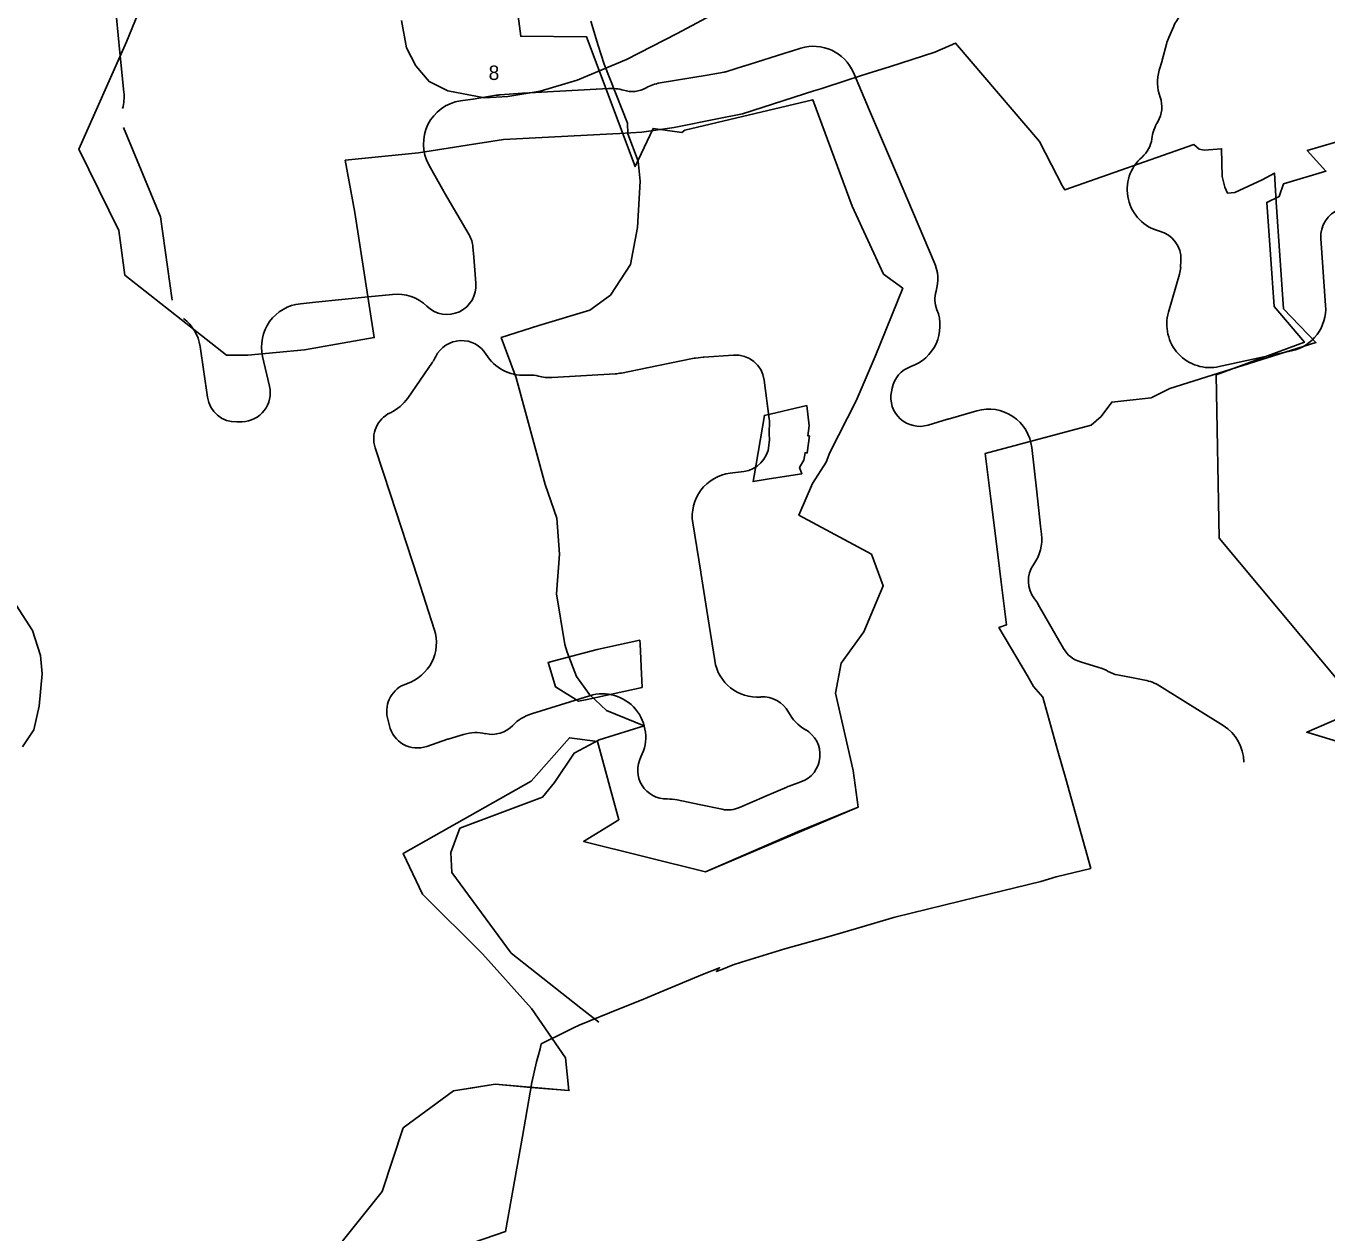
# Model space of a CAD drawing. Extents: x -445049 to -436194, y -1142460 to -1129816.
# Drawn here: x -443023 to -442122, y -1133134 to -1132297 of the extents above; entities that cross this region are included whole.
import ezdxf

# ---------------------------------------------------------------- set-up
doc = ezdxf.new("R2010")
doc.units = 0
for name, color, linetype in [('Vrstva 10', 7, 'Continuous'), ('Vrstva 23', 7, 'Continuous'), ('Vrstva 26', 7, 'Continuous'), ('Vrstva 51', 7, 'Continuous'), ('Vrstva 7', 7, 'Continuous'), ('Vrstva 8', 7, 'Continuous'), ('Vrstva 9', 7, 'Continuous')]:
    doc.layers.add(name, color=color, linetype=linetype)

msp = doc.modelspace()

# ---------------------------------------------------------------- linework, layer by layer
at = {"layer": 'Vrstva 10'}
msp.add_lwpolyline([(-442109.03, -1132794.68), (-442135.55, -1132786.74), (-442097.52, -1132770.3), (-442196.18, -1132652.14), (-442198.38, -1132539.08), (-442137.12, -1132516.56), (-442158.19, -1132491.81), (-442163.27, -1132419.71), (-442154.54, -1132415.62), (-442151.59, -1132406.77), (-442122.25, -1132397.95), (-442135.23, -1132383.63), (-442097.99, -1132372.93)], dxfattribs=at)
at = {"layer": 'Vrstva 23'}
for p, q in [((-442957.74, -1132315.82), (-442960.18, -1132291.9)), ((-442227.66, -1132297.45), (-442231.2, -1132305.52)), ((-442232.75, -1132310.02), (-442235.63, -1132321.09)), ((-442954.94, -1132343.31), (-442957.74, -1132315.82)), ((-442493.43, -1132315.14), (-442525.56, -1132325.32)), ((-442486.1, -1132312.86), (-442493.26, -1132315.09)), ((-442235.8, -1132321.69), (-442237.68, -1132328.11)), ((-442539.18, -1132329.4), (-442550.89, -1132331.43)), ((-442525.63, -1132325.34), (-442536.62, -1132328.79)), ((-442438.41, -1132355.92), (-442449.62, -1132329.71)), ((-442551.01, -1132331.46), (-442583.52, -1132336.89)), ((-442713.29, -1132348.06), (-442721.83, -1132349.33)), ((-442696.97, -1132345.45), (-442713.06, -1132348.03)), ((-442678.78, -1132344.02), (-442694.4, -1132345.15)), ((-442619.3, -1132340.69), (-442678.28, -1132343.99)), ((-442419.09, -1132401.26), (-442438.4, -1132355.96)), ((-442743.65, -1132393.58), (-442733.12, -1132412.52)), ((-442393.54, -1132460.98), (-442419.08, -1132401.29)), ((-442732.79, -1132413.1), (-442715.81, -1132442.13)), ((-442122.5, -1132491.05), (-442125.76, -1132444.58)), ((-442713.13, -1132450.74), (-442712.63, -1132457.45)), ((-442712.62, -1132457.65), (-442711.15, -1132475.65)), ((-442222.69, -1132459.74), (-442222.89, -1132464.67)), ((-442223.67, -1132469.45), (-442231.32, -1132495.7)), ((-442768.9, -1132483.34), (-442785.65, -1132485.04)), ((-442822.34, -1132488.76), (-442832.71, -1132489.83)), ((-442785.65, -1132485.04), (-442822.28, -1132488.75)), ((-442897.11, -1132554.65), (-442902.23, -1132519.43)), ((-442858.87, -1132526.42), (-442854.12, -1132547)), ((-442592.49, -1132534.2), (-442560.97, -1132527.8)), ((-442559.04, -1132527.5), (-442553.72, -1132526.95)), ((-442553.15, -1132526.9), (-442532.68, -1132525.39)), ((-442196.12, -1132533.4), (-442146.02, -1132522.46)), ((-442758.36, -1132555.17), (-442741.27, -1132530.36)), ((-442741.27, -1132530.35), (-442741.17, -1132530.21)), ((-442610.33, -1132537.86), (-442592.53, -1132534.2)), ((-442676.81, -1132539.4), (-442674.08, -1132539.27)), ((-442658.19, -1132540.96), (-442614.62, -1132538.42)), ((-442511.38, -1132542.74), (-442507.85, -1132569.69)), ((-442423.3, -1132550.9), (-442422.8, -1132548.36)), ((-442364.18, -1132564.03), (-442383.92, -1132569.71)), ((-442872.96, -1132571.65), (-442876.71, -1132571.76)), ((-442384.3, -1132569.83), (-442397.89, -1132573.94)), ((-442770.36, -1132621.97), (-442780.93, -1132589.7)), ((-442507.87, -1132585.65), (-442508.11, -1132588.09)), ((-442322.63, -1132620.13), (-442326.06, -1132589.51)), ((-442525.49, -1132606.01), (-442535.04, -1132607.23)), ((-442751.63, -1132679.36), (-442770.35, -1132622)), ((-442319.97, -1132643.84), (-442322.63, -1132620.14)), ((-442560.87, -1132641.74), (-442555.38, -1132675.91)), ((-442319.32, -1132649.42), (-442319.96, -1132643.94)), ((-442739.92, -1132715.25), (-442751.62, -1132679.37)), ((-442555.37, -1132675.96), (-442550.51, -1132706.63)), ((-442304.03, -1132728.71), (-442321.53, -1132698.1)), ((-442550.51, -1132706.63), (-442545.69, -1132737.06)), ((-442279.61, -1132741.74), (-442292.35, -1132737.96)), ((-442255.77, -1132749.05), (-442266.65, -1132746.98)), ((-442247.76, -1132750.57), (-442255.77, -1132749.05)), ((-442632.38, -1132761.4), (-442672.71, -1132773.93)), ((-442193.37, -1132782.02), (-442237.52, -1132754.57)), ((-442771.06, -1132782.17), (-442772.36, -1132776.66)), ((-442719.65, -1132788.24), (-442729.71, -1132791.27)), ((-442730.73, -1132791.6), (-442745.14, -1132796.51)), ((-442495.73, -1132824.7), (-442511.06, -1132831.2)), ((-442485.94, -1132821.12), (-442494.19, -1132824.1)), ((-442556.5, -1132836.74), (-442571.71, -1132833.56)), ((-442511.41, -1132831.35), (-442528.41, -1132838.82)), ((-442540.54, -1132840.08), (-442556.5, -1132836.74))]:
    msp.add_line(p, q, dxfattribs=at)
msp.add_lwpolyline([(-442921.64, -1132487.44), (-442929.57, -1132429.68), (-442955.18, -1132367.68)], dxfattribs=at)
for centre, radius, start, end in [((-442200.18, -1132309.49), 30, 136.62933, 156.33647), ((-442477.2, -1132341.51), 30, 23.15168, 107.25965), ((-442203.72, -1132317.56), 30, 156.33647, 165.43444), ((-442937.84, -1132313.79), 20, 185.82227, 185.82544), ((-442484.36, -1132343.73), 30, 107.25965, 107.58988), ((-442254.99, -1132316.06), 20, 343.64627, 345.43444), ((-442542.6, -1132309.7), 20, 279.83922, 287.37641), ((-442531.6, -1132306.26), 20, 287.37641, 287.58988), ((-442208.89, -1132336.55), 30, 163.64627, 199.84662), ((-442578.57, -1132366.48), 30, 99.49232, 119.21234), ((-442554.31, -1132311.73), 20, 279.49232, 279.83922), ((-442984.78, -1132346.35), 30, 344.10309, 5.82544), ((-442716.22, -1132328.28), 20, 278.44397, 279.08948), ((-442692.23, -1132375.07), 30, 94.15381, 99.08948), ((-442676.61, -1132373.94), 30, 93.19748, 94.15381), ((-442617.62, -1132370.64), 30, 72.95959, 93.19748), ((-442602.97, -1132322.84), 20, 252.95959, 299.21234), ((-442255.92, -1132353.53), 20, 328.95738, 19.84662), ((-442717.43, -1132379), 30, 98.44397, 209.06864), ((-442466, -1132367.72), 30, 23.07993, 23.15168), ((-442212.78, -1132379.49), 30.35, 148.95738, 172.76176), ((-442262.73, -1132373.15), 20, 310.92226, 352.76176), ((-442230.13, -1132410.76), 29.77, 130.92226, 255.41229), ((-442400.69, -1132393.42), 20, 203.07993, 203.16557), ((-442706.9, -1132397.95), 30, 209.06864, 210.32596), ((-442105.81, -1132443.17), 20, 110.6205, 184.01796), ((-442191.84, -1132439.88), 50, 177.60823, 177.64508), ((-442733.08, -1132452.22), 20, 4.259, 30.32596), ((-442242.67, -1132458.92), 20, 357.64508, 75.41229), ((-442682.71, -1132455.22), 30, 184.25897, 184.65397), ((-442421.12, -1132472.78), 30, 343.82915, 23.16557), ((-442242.87, -1132463.85), 20, 343.74529, 357.64508), ((-442765.87, -1132513.19), 30, 45.9152, 95.7926), ((-442731.08, -1132477.27), 20, 225.9152, 4.65396), ((-442373.1, -1132486.71), 20, 163.82915, 201.5094), ((-442829.64, -1132519.67), 30, 95.88775, 192.9966), ((-442819.26, -1132518.6), 30, 95.78982, 95.88775), ((-442787.67, -1132465.14), 20, 275.78982, 275.7926), ((-442152.42, -1132493.15), 30, 282.32123, 4.01796), ((-442931.92, -1132523.75), 30, 8.27726, 52.36246), ((-442419.62, -1132505.04), 30, 289.19359, 21.5094), ((-442202.52, -1132504.09), 30, 163.74529, 282.32123), ((-442721.06, -1132535.36), 20, 31.22603, 153.67299), ((-442765.87, -1132513.19), 30, 325.43977, 333.67299), ((-442678.3, -1132509.44), 30, 211.22603, 272.84214), ((-442556.99, -1132547.4), 20, 95.88585, 101.47902), ((-442551.67, -1132546.85), 20, 94.23101, 95.88585), ((-442531.21, -1132545.33), 20, 7.46163, 94.23101), ((-442724.8, -1132541.7), 20, 145.43977, 145.44951), ((-442616.36, -1132508.47), 30, 273.3252, 281.61099), ((-442588.5, -1132553.8), 20, 101.47902, 101.61099), ((-442403.18, -1132552.26), 20, 109.19359, 168.76185), ((-442673.09, -1132559.24), 20, 74.74496, 92.84214), ((-442659.93, -1132511.01), 30, 254.74496, 273.3252), ((-442877.32, -1132551.77), 20, 188.27726, 271.74737), ((-442873.57, -1132551.66), 20, 271.74737, 13.18493), ((-442824.89, -1132540.25), 30, 192.9966, 193.18493), ((-442783.07, -1132538.16), 30, 295.00864, 325.44951), ((-442403.68, -1132554.8), 20, 168.76185, 286.83942), ((-442355.87, -1132592.85), 30, 6.39032, 106.07109), ((-442761.93, -1132583.47), 20, 115.00864, 198.13953), ((-442527.68, -1132572.29), 20, 353.04978, 7.46163), ((-442375.61, -1132598.54), 30, 106.07109, 106.83942), ((-442478.05, -1132578.34), 30, 173.04978, 186.09223), ((-442527.76, -1132583.64), 20, 354.25098, 6.09223), ((-442528.02, -1132586.17), 20, 277.27102, 354.34773), ((-442478.26, -1132591.09), 30, 174.25098, 174.34773), ((-442531.25, -1132636.98), 30, 97.27102, 189.13006), ((-442798.87, -1132631.31), 30, 18.08071, 18.13953), ((-442302.75, -1132617.91), 20, 186.39032, 186.3974), ((-442300.09, -1132641.61), 20, 186.3974, 186.6774), ((-442349.11, -1132652.91), 30, 324.52822, 6.6774), ((-442308.39, -1132681.93), 20, 144.52822, 218.41396), ((-442780.14, -1132688.67), 30, 18.05894, 18.08071), ((-442575.12, -1132679.08), 20, 8.99993, 9.13006), ((-442347.57, -1132712.99), 30, 29.76045, 38.41396), ((-442570.26, -1132709.76), 20, 8.99472, 8.99993), ((-442768.45, -1132724.55), 30, 288.12384, 18.05894), ((-442286.66, -1132718.79), 20, 209.75853, 253.49032), ((-442516.06, -1132732.37), 30, 188.99472, 274.36892), ((-442288.14, -1132770.5), 30, 59.69874, 73.49032), ((-442262.91, -1132727.33), 20, 239.69874, 259.22819), ((-442752.89, -1132772.07), 20, 108.12384, 193.25843), ((-442252.03, -1132729.4), 20, 259.22819, 259.2388), ((-442253.36, -1132780.04), 30, 58.12147, 79.2388), ((-442623.48, -1132790.05), 30, 332.75604, 107.25158), ((-442512.25, -1132782.22), 20, 27.9218, 94.36892), ((-442663.81, -1132802.58), 30, 107.25158, 136.50496), ((-442468.07, -1132758.81), 30, 207.9218, 240.46264), ((-442751.59, -1132777.58), 20, 193.25843, 288.82418), ((-442710.98, -1132816.96), 30, 77.4082, 106.78491), ((-442700.08, -1132768.16), 20, 257.4082, 316.50496), ((-442492.72, -1132802.31), 20, 289.82444, 60.46264), ((-442209.21, -1132807.5), 30, 0.15915, 58.12147), ((-442721.05, -1132820), 30, 106.78491, 108.82418), ((-442579.03, -1132812.94), 20, 152.75604, 271.35626), ((-442484.02, -1132852.32), 30, 109.82444, 112.97972), ((-442577.85, -1132862.93), 30, 78.18999, 91.35626), ((-442499.35, -1132858.82), 30, 112.97972, 113.70018), ((-442552.41, -1132817.17), 20, 258.18999, 258.19838), ((-442536.45, -1132820.5), 20, 258.19838, 293.70018)]:
    msp.add_arc(centre, radius, start, end, dxfattribs=at)
at = {"layer": 'Vrstva 26'}
for points in [[(-442631.56, -1132294), (-442626.31, -1132311), (-442622.28, -1132324), (-442606.19, -1132364.75), (-442605.81, -1132372.12), (-442598.81, -1132391), (-442597.34, -1132405)], [(-442597.34, -1132405), (-442599.16, -1132437.12), (-442603.94, -1132462.75), (-442617.94, -1132484), (-442632.25, -1132494.38), (-442667.5, -1132505), (-442693.5, -1132513.25), (-442683.22, -1132541.12), (-442663.03, -1132615.12), (-442654.97, -1132638.38), (-442653.16, -1132663.38), (-442655.34, -1132690.88), (-442649.47, -1132726), (-442648, -1132731.12), (-442641.53, -1132748.12), (-442632.38, -1132760.62), (-442620.62, -1132771.62), (-442594.59, -1132782.25), (-442625.78, -1132791.88), (-442643, -1132801.12), (-442656.56, -1132821.62), (-442665, -1132831.62), (-442722.22, -1132853.25), (-442728.47, -1132870), (-442727.72, -1132883.88), (-442686.66, -1132939.75), (-442638.5, -1132977.75), (-442625.9, -1132987.6)]]:
    msp.add_lwpolyline(points, dxfattribs=at)
at = {"layer": 'Vrstva 51'}
for points in [[(-442762.66, -1132293.74), (-442759.13, -1132312.56), (-442752.64, -1132325), (-442743.57, -1132335.99), (-442730.45, -1132342.34), (-442705.24, -1132347.12), (-442689.1, -1132346.27), (-442666.56, -1132342.61), (-442640.85, -1132335.06), (-442606.79, -1132320.72), (-442571.63, -1132302.75), (-442541.55, -1132286.46)], [(-443025.22, -1132796.81), (-443017.38, -1132785.12), (-443013.68, -1132768.61), (-443011.59, -1132746.25), (-443012.68, -1132733.48), (-443018.34, -1132716.27), (-443029.71, -1132698.63)]]:
    msp.add_lwpolyline(points, dxfattribs=at)
at = {"layer": 'Vrstva 7'}
for points in [[(-442922.59, -1132233.93), (-442953.25, -1132308.47), (-442986.29, -1132382.77), (-442958.54, -1132439.22), (-442954.29, -1132470.17), (-442883.88, -1132525.49), (-442869.19, -1132525.36), (-442829.94, -1132521.75), (-442781.57, -1132513.28), (-442795.03, -1132426.67), (-442801.63, -1132390.42), (-442750.9, -1132385.4), (-442717.09, -1132380.1), (-442691.93, -1132376.15), (-442616.35, -1132372.16), (-442616.35, -1132372.16), (-442611.45, -1132371.9), (-442596.16, -1132371.1), (-442573.78, -1132367.82), (-442543.93, -1132361.77), (-442526.36, -1132358.21), (-442477.04, -1132342.43), (-442472.26, -1132340.9), (-442453.33, -1132334.85), (-442438.85, -1132330.22), (-442424.65, -1132325.68), (-442393.28, -1132315.65), (-442378.77, -1132309.31), (-442320.57, -1132377.44), (-442312.27, -1132393.66), (-442304.72, -1132408.4), (-442303.09, -1132411.01), (-442213.73, -1132379.55), (-442210.06, -1132382.66), (-442206.65, -1132383.46), (-442194.59, -1132382.53), (-442194.21, -1132401.61), (-442192.39, -1132409.19), (-442190.46, -1132413.21), (-442185.39, -1132412.76), (-442166.39, -1132404.06), (-442157.99, -1132399.36), (-442156.75, -1132419.42), (-442151.64, -1132493.29), (-442129.19, -1132516.78), (-442230.4, -1132548.48), (-442243.24, -1132554.95), (-442270.61, -1132557.94), (-442277.91, -1132567.95), (-442284.89, -1132573.96), (-442358.4, -1132593.69), (-442354.45, -1132625), (-442350.74, -1132654.35), (-442347.15, -1132682.73), (-442343.44, -1132712.19), (-442348.83, -1132714.24), (-442328.94, -1132747.55), (-442324.92, -1132754.94), (-442318.3, -1132762.38), (-442307.93, -1132799.8), (-442302.55, -1132818.91), (-442285.23, -1132881.09)], [(-442712.69, -1133140.21), (-442690.54, -1133132.6), (-442678.94, -1133066.74), (-442672.35, -1133029.29), (-442669.09, -1133015.08), (-442667.79, -1133010.13), (-442666.7, -1133005.99), (-442665.82, -1133002.63), (-442648.47, -1132994.02), (-442645.79, -1132992.69), (-442643.47, -1132991.54), (-442639.52, -1132989.58), (-442611.14, -1132977.99), (-442596.71, -1132972.33), (-442583.36, -1132966.7), (-442554.21, -1132954.62), (-442542.26, -1132949.89), (-442544.59, -1132952.4), (-442540.74, -1132951.01), (-442532.91, -1132947.79), (-442527.04, -1132945.99), (-442497.2, -1132936.83), (-442466.36, -1132928.28), (-442447.46, -1132922.71), (-442420.82, -1132914.86), (-442364.23, -1132900.95), (-442319.76, -1132890.16), (-442309.05, -1132886.83), (-442285.23, -1132881.09), (-442302.55, -1132818.91), (-442307.93, -1132799.8), (-442318.3, -1132762.38), (-442324.92, -1132754.94), (-442328.94, -1132747.55), (-442348.83, -1132714.24), (-442343.44, -1132712.19), (-442347.15, -1132682.73), (-442350.74, -1132654.35), (-442354.45, -1132625), (-442358.4, -1132593.69), (-442284.89, -1132573.96), (-442277.91, -1132567.95), (-442270.61, -1132557.94), (-442243.24, -1132554.95), (-442230.4, -1132548.48), (-442129.19, -1132516.78), (-442151.64, -1132493.29), (-442156.75, -1132419.42), (-442157.99, -1132399.36), (-442166.39, -1132404.06), (-442185.39, -1132412.76), (-442190.46, -1132413.21), (-442192.39, -1132409.19), (-442194.21, -1132401.61), (-442194.59, -1132382.53), (-442206.65, -1132383.46), (-442210.06, -1132382.66), (-442213.73, -1132379.55), (-442303.09, -1132411.01), (-442304.72, -1132408.4), (-442312.27, -1132393.66), (-442320.57, -1132377.44), (-442378.77, -1132309.31), (-442393.28, -1132315.65), (-442424.65, -1132325.68), (-442438.85, -1132330.22), (-442453.33, -1132334.85), (-442472.26, -1132340.9), (-442477.04, -1132342.43), (-442526.36, -1132358.21), (-442543.93, -1132361.77), (-442573.78, -1132367.82), (-442596.16, -1132371.1), (-442611.45, -1132371.9), (-442616.35, -1132372.16), (-442691.93, -1132376.15), (-442717.09, -1132380.1), (-442750.9, -1132385.4), (-442801.63, -1132390.42), (-442795.03, -1132426.67), (-442781.57, -1132513.28), (-442829.94, -1132521.75), (-442869.19, -1132525.36), (-442883.88, -1132525.49), (-442954.29, -1132470.17), (-442958.54, -1132439.22), (-442986.29, -1132382.77), (-442953.25, -1132308.47), (-442922.59, -1132233.93)], [(-442712.69, -1133140.21), (-442690.54, -1133132.6), (-442678.94, -1133066.74), (-442672.35, -1133029.29), (-442669.09, -1133015.08), (-442667.79, -1133010.13), (-442666.7, -1133005.99), (-442665.82, -1133002.63), (-442648.47, -1132994.02), (-442645.79, -1132992.69), (-442643.47, -1132991.54), (-442639.52, -1132989.58), (-442611.14, -1132977.99), (-442596.71, -1132972.33), (-442583.36, -1132966.7), (-442554.21, -1132954.62), (-442542.26, -1132949.89), (-442544.59, -1132952.4), (-442540.74, -1132951.01), (-442532.91, -1132947.79), (-442527.04, -1132945.99), (-442497.2, -1132936.83), (-442466.36, -1132928.28), (-442447.46, -1132922.71), (-442420.82, -1132914.86), (-442364.23, -1132900.95), (-442319.76, -1132890.16), (-442309.05, -1132886.83), (-442285.23, -1132881.09), (-442302.55, -1132818.91), (-442307.93, -1132799.8), (-442318.3, -1132762.38), (-442324.92, -1132754.94), (-442328.94, -1132747.55), (-442348.83, -1132714.24), (-442343.44, -1132712.19), (-442347.15, -1132682.73), (-442350.74, -1132654.35), (-442354.45, -1132625), (-442358.4, -1132593.69), (-442284.89, -1132573.96), (-442277.91, -1132567.95), (-442270.61, -1132557.94), (-442243.24, -1132554.95), (-442230.4, -1132548.48), (-442129.19, -1132516.78), (-442151.64, -1132493.29), (-442156.75, -1132419.42), (-442157.99, -1132399.36), (-442166.39, -1132404.06), (-442185.39, -1132412.76), (-442190.46, -1132413.21), (-442192.39, -1132409.19), (-442194.21, -1132401.61), (-442194.59, -1132382.53), (-442206.65, -1132383.46), (-442210.06, -1132382.66), (-442213.73, -1132379.55), (-442303.09, -1132411.01), (-442304.72, -1132408.4), (-442312.27, -1132393.66), (-442320.57, -1132377.44), (-442378.77, -1132309.31), (-442393.28, -1132315.65), (-442424.65, -1132325.68), (-442438.85, -1132330.22), (-442453.33, -1132334.85), (-442472.26, -1132340.9), (-442477.04, -1132342.43), (-442526.36, -1132358.21), (-442543.93, -1132361.77), (-442573.78, -1132367.82), (-442596.16, -1132371.1), (-442611.45, -1132371.9), (-442616.35, -1132372.16), (-442691.93, -1132376.15), (-442717.09, -1132380.1), (-442750.9, -1132385.4), (-442801.63, -1132390.42), (-442795.03, -1132426.67), (-442781.57, -1132513.28), (-442829.94, -1132521.75), (-442869.19, -1132525.36), (-442883.88, -1132525.49), (-442954.29, -1132470.17), (-442958.54, -1132439.22), (-442986.29, -1132382.77), (-442953.25, -1132308.47), (-442922.59, -1132233.93)], [(-442481.77, -1132560.24), (-442480.15, -1132574.46), (-442481.23, -1132581.27), (-442480.06, -1132581.44), (-442481.54, -1132593.18), (-442483.12, -1132593.13), (-442483.91, -1132598.1), (-442486.83, -1132603.3), (-442485.38, -1132607.73), (-442507.9, -1132611.25), (-442519.13, -1132613.01), (-442518.26, -1132609.08), (-442511.21, -1132567.18), (-442481.77, -1132560.24)], [(-442597.5, -1132722.99), (-442597.37, -1132725.74), (-442596.92, -1132735.58), (-442596.65, -1132741.41), (-442596, -1132755.59), (-442634.02, -1132763.9), (-442640.09, -1132765.23), (-442655.95, -1132755.3), (-442660.01, -1132742.11), (-442661.14, -1132738.48), (-442656.8, -1132737.33), (-442627.12, -1132729.44), (-442597.5, -1132722.99)]]:
    msp.add_lwpolyline(points, dxfattribs=at)
for points in [[(-442481.77, -1132560.24), (-442511.21, -1132567.18), (-442518.26, -1132609.08), (-442519.13, -1132613.01), (-442507.9, -1132611.25), (-442485.38, -1132607.73), (-442486.83, -1132603.3), (-442483.91, -1132598.1), (-442483.12, -1132593.13), (-442481.54, -1132593.18), (-442480.06, -1132581.44), (-442481.23, -1132581.27), (-442480.15, -1132574.46)], [(-442597.5, -1132722.99), (-442627.12, -1132729.44), (-442656.8, -1132737.33), (-442661.14, -1132738.48), (-442660.01, -1132742.11), (-442655.95, -1132755.3), (-442640.09, -1132765.23), (-442634.02, -1132763.9), (-442596, -1132755.59), (-442596.65, -1132741.41), (-442596.92, -1132735.58), (-442597.37, -1132725.74)]]:
    msp.add_lwpolyline(points, close=True, dxfattribs=at)
at = {"layer": 'Vrstva 8'}
for points in [[(-442686.56, -1132255.99), (-442680.09, -1132304.51), (-442634.44, -1132305.05), (-442600.88, -1132394.78), (-442588.34, -1132368.36), (-442568.38, -1132371.16), (-442566.42, -1132369.58), (-442477.76, -1132348.51), (-442450.55, -1132422.25), (-442428.65, -1132469.3), (-442415.39, -1132479.09), (-442434.45, -1132526.47), (-442447.62, -1132557.04), (-442465.98, -1132592.97), (-442468.52, -1132599.61), (-442477.97, -1132614.28), (-442487.31, -1132636.43), (-442437.16, -1132663.37), (-442428.9, -1132685.25), (-442442.48, -1132717.15), (-442457.98, -1132738.95), (-442462.06, -1132759.7), (-442449.79, -1132813.19), (-442446.31, -1132838.66), (-442552.14, -1132883.33), (-442636.56, -1132862.44), (-442612.09, -1132847.34), (-442626.96, -1132793.03), (-442646.29, -1132790.53), (-442672.85, -1132820.57), (-442761.57, -1132870.8), (-442748.21, -1132898.79), (-442706.65, -1132940.19), (-442672.59, -1132978.12), (-442658.25, -1132998.9)], [(-442658.25, -1132998.9), (-442649.08, -1133012.18), (-442646.72, -1133034.99), (-442672.95, -1133032.71)], [(-442672.95, -1133032.71), (-442697.66, -1133030.53), (-442713.26, -1133033.01), (-442726.59, -1133035.13), (-442761.52, -1133060.83), (-442776.12, -1133104.83), (-442805.7, -1133141.9), (-442836.23, -1133168.46), (-442848.81, -1133188.3), (-442862.95, -1133235.36), (-442888.56, -1133275.04), (-442931.25, -1133319.68), (-442936.73, -1133333.97)]]:
    msp.add_lwpolyline(points, dxfattribs=at)
at = {"layer": 'Vrstva 9'}
for points in [[(-442805.7, -1133141.9), (-442776.12, -1133104.83), (-442761.52, -1133060.83), (-442726.59, -1133035.13), (-442697.66, -1133030.53), (-442646.72, -1133034.99), (-442649.08, -1133012.18), (-442672.59, -1132978.12), (-442706.65, -1132940.19), (-442748.21, -1132898.79), (-442761.57, -1132870.8), (-442672.85, -1132820.57), (-442646.29, -1132790.53), (-442626.96, -1132793.03), (-442612.09, -1132847.34), (-442636.56, -1132862.44), (-442552.14, -1132883.33), (-442488.27, -1132855.66), (-442446.31, -1132838.66), (-442449.79, -1132813.19), (-442462.06, -1132759.7), (-442457.98, -1132738.95), (-442442.48, -1132717.15), (-442428.9, -1132685.25), (-442437.16, -1132663.37), (-442487.31, -1132636.43), (-442477.97, -1132614.28), (-442468.52, -1132599.61), (-442465.98, -1132592.97), (-442447.62, -1132557.04), (-442434.45, -1132526.47), (-442415.39, -1132479.09), (-442428.65, -1132469.3), (-442450.55, -1132422.25), (-442477.76, -1132348.51), (-442566.42, -1132369.58), (-442568.38, -1132371.16), (-442588.34, -1132368.36), (-442600.88, -1132394.78), (-442634.44, -1132305.05), (-442680.09, -1132304.51), (-442686.56, -1132255.99)], [(-442097.99, -1132372.93), (-442135.23, -1132383.63), (-442122.25, -1132397.95), (-442151.59, -1132406.77), (-442154.54, -1132415.62), (-442163.27, -1132419.71), (-442158.19, -1132491.81), (-442137.12, -1132516.56), (-442198.38, -1132539.08), (-442196.18, -1132652.14), (-442097.52, -1132770.3), (-442135.55, -1132786.74), (-442128.79, -1132788.76)]]:
    msp.add_lwpolyline(points, dxfattribs=at)

# ---------------------------------------------------------------- texts
at = {"layer": 'Vrstva 51'}
msp.add_text('8', height=10, dxfattribs=at).set_placement((-442702.31, -1132334.84))

doc.saveas('drawing.dxf')
